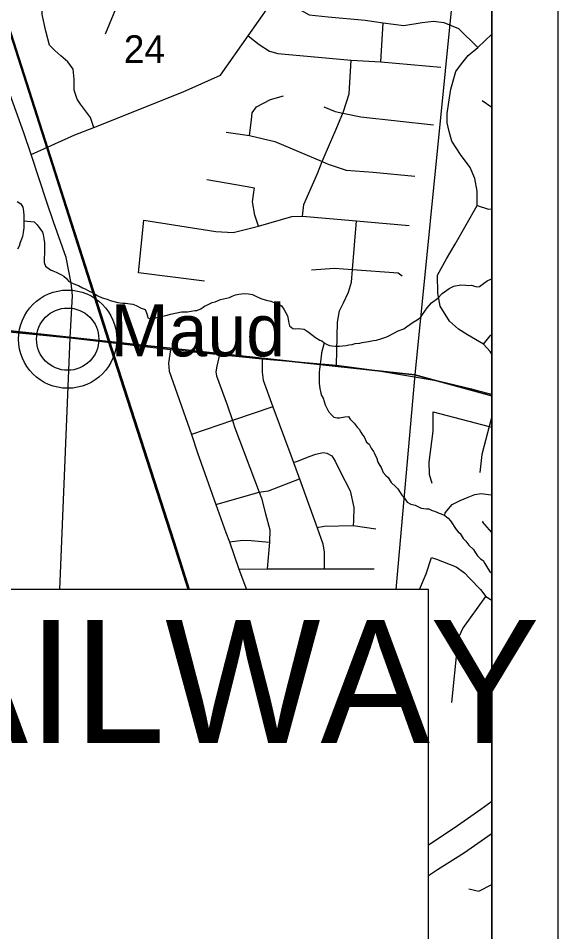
# Model space of a CAD drawing. Extents: x 0 to 34, y 0 to 22.
# Drawn here: x 8.182 to 9, y 18.207 to 19.591 of the extents above; entities that cross this region are included whole.
import ezdxf

# ---------------------------------------------------------------- set-up
doc = ezdxf.new("R2010")
doc.units = 0
for name, color, linetype in [('Default', 7, 'Continuous'), ('GM_X_County_Road', 7, 'Continuous'), ('GM_X_Interstate_Route', 7, 'Continuous'), ('GM_X_Minor_River', 7, 'Continuous'), ('GM_X_Rail_Line', 7, 'Continuous'), ('GM_X_Section', 7, 'Continuous'), ('GM_X_Section_Text', 7, 'Continuous'), ('GM_X_Township_Road', 7, 'Continuous'), ('GM_X_Unincorporated', 7, 'Continuous'), ('GM_X_Unincorporated_Location', 7, 'Continuous'), ('GM_X_Unincorporated_Text', 7, 'Continuous'), ('SH_Cut_Line', 7, 'Continuous'), ('SH_Data', 7, 'Continuous'), ('SH_Text', 7, 'Continuous')]:
    doc.layers.add(name, color=color, linetype=linetype)

msp = doc.modelspace()

# ---------------------------------------------------------------- linework, layer by layer
at = {"layer": 'Default'}
msp.add_lwpolyline([(8.9, 19.0188), (8.9, 19.9702), (8.8752, 19.9725), (8.7834, 19.051)], close=True, dxfattribs=at)
msp.add_lwpolyline([(8.7045, 18.1592), (8.6934, 18.0333), (8.9, 17.9772), (8.9, 19.0188), (8.7834, 19.051), (8.7546, 18.7255)], dxfattribs=at)
at = {"layer": 'GM_X_County_Road'}
for p, q in [((8.2452, 18.7255), (8.261, 19.1068)), ((8.8766, 19.0276), (8.9, 19.0217))]:
    msp.add_line(p, q, dxfattribs=at)
for points in [[(8.5308, 19.5646), (8.5777, 19.6316), (8.6345, 19.7128)], [(8.2019, 19.3849), (8.2683, 19.4144), (8.2969, 19.4257), (8.4325, 19.4794), (8.4891, 19.5049), (8.5308, 19.5646)], [(8.261, 19.1068), (8.2646, 19.1709), (8.2625, 19.1897), (8.2552, 19.2287), (8.2359, 19.2826), (8.2259, 19.3127), (8.2019, 19.3849)], [(7.9926, 19.134), (8.0146, 19.1319), (8.0648, 19.1263), (8.261, 19.1068)], [(8.261, 19.1068), (8.413, 19.089), (8.4873, 19.0817), (8.5519, 19.075), (8.6646, 19.0656), (8.7258, 19.0576), (8.8186, 19.0419), (8.8692, 19.0295), (8.8766, 19.0276)]]:
    msp.add_lwpolyline(points, dxfattribs=at)
at = {"layer": 'GM_X_Interstate_Route'}
for points in [[(8.8041, 18.3388), (8.8432, 18.3646), (8.8836, 18.3928), (8.9, 18.405)], [(8.8041, 18.2924), (8.818, 18.3014), (8.8585, 18.3272), (8.8989, 18.3555), (8.9, 18.3563)]]:
    msp.add_lwpolyline(points, dxfattribs=at)
at = {"layer": 'GM_X_Minor_River'}
for points in [[(8.1807, 19.3137), (8.1862, 19.3097), (8.1895, 19.3047), (8.1905, 19.2986), (8.1907, 19.2921), (8.1906, 19.2887), (8.1908, 19.2841), (8.1906, 19.2784), (8.1909, 19.2735), (8.1904, 19.2701), (8.1899, 19.2663), (8.1886, 19.2606), (8.1873, 19.2565), (8.1853, 19.2512), (8.1836, 19.2459), (8.1812, 19.2411)], [(8.1908, 19.2841), (8.2067, 19.2825), (8.2112, 19.2782), (8.2152, 19.2724), (8.2192, 19.2669), (8.2202, 19.2635), (8.2212, 19.2573), (8.2221, 19.2509), (8.222, 19.2467), (8.2222, 19.2413), (8.2216, 19.2208), (8.2238, 19.2155), (8.2312, 19.2099), (8.2349, 19.2083), (8.2398, 19.2062), (8.244, 19.2046), (8.2477, 19.2026), (8.2514, 19.2002), (8.2555, 19.1966), (8.2584, 19.1927), (8.2622, 19.1907), (8.2689, 19.1875), (8.2734, 19.1862), (8.2798, 19.1829), (8.2839, 19.1813), (8.2907, 19.1769), (8.2952, 19.1756), (8.3019, 19.1709), (8.3094, 19.1676), (8.3173, 19.1655), (8.3214, 19.1634), (8.3331, 19.1604), (8.3407, 19.1594), (8.3449, 19.1593), (8.3521, 19.1583), (8.3562, 19.1578), (8.3611, 19.1561), (8.3686, 19.1521), (8.3746, 19.15), (8.3768, 19.145), (8.3778, 19.1416), (8.3788, 19.1374), (8.3837, 19.1353), (8.3894, 19.1366), (8.394, 19.138), (8.4078, 19.1414), (8.4132, 19.1428), (8.4296, 19.1461), (8.4391, 19.1465), (8.4498, 19.1481), (8.4532, 19.1484), (8.459, 19.1509), (8.4645, 19.1549), (8.4683, 19.1563), (8.476, 19.1602), (8.4806, 19.1616), (8.4887, 19.1648), (8.4933, 19.1662), (8.5025, 19.1682), (8.5067, 19.1699), (8.5117, 19.1721), (8.5167, 19.173), (8.5247, 19.1743), (8.5312, 19.1737), (8.5372, 19.1724), (8.5413, 19.1704), (8.55, 19.1667), (8.5579, 19.1642), (8.5654, 19.1624), (8.5729, 19.1592), (8.5774, 19.1579), (8.5815, 19.1555), (8.5848, 19.1501), (8.5881, 19.145), (8.5906, 19.14), (8.5919, 19.1324), (8.5922, 19.1289), (8.5932, 19.1251), (8.5984, 19.1211), (8.6018, 19.1203), (8.6068, 19.1209), (8.6113, 19.1207), (8.6155, 19.1199), (8.6218, 19.1159), (8.633, 19.1072), (8.6393, 19.1035), (8.6427, 19.1023), (8.646, 19.0995), (8.6494, 19.0972), (8.6543, 19.0951), (8.6577, 19.0946), (8.6634, 19.0941), (8.6691, 19.0943), (8.674, 19.0949), (8.6794, 19.0955), (8.6836, 19.0961), (8.6885, 19.0967), (8.6931, 19.0981), (8.7, 19.099), (8.7038, 19.0997), (8.713, 19.1013)], [(8.713, 19.1013), (8.721, 19.1029), (8.7252, 19.1036), (8.7321, 19.1056), (8.7394, 19.1077), (8.7429, 19.1095), (8.7514, 19.1138), (8.7583, 19.1174), (8.7668, 19.1206), (8.771, 19.1238), (8.7807, 19.1308), (8.7869, 19.1344), (8.7924, 19.1384), (8.7951, 19.1421), (8.8023, 19.1525), (8.8086, 19.1599), (8.8183, 19.1672), (8.825, 19.1743), (8.8355, 19.1819), (8.8424, 19.1851), (8.8531, 19.1871), (8.8607, 19.1869), (8.8649, 19.1864), (8.8691, 19.1866), (8.8736, 19.1853), (8.8773, 19.1841), (8.8812, 19.1847), (8.8877, 19.1891), (8.8932, 19.1935), (8.8986, 19.1956), (8.9, 19.1961)], [(8.646, 19.0995), (8.6418, 19.0841), (8.6412, 19.0784), (8.6388, 19.0595), (8.6382, 19.0542), (8.6384, 19.0454), (8.6385, 19.0382), (8.6391, 19.0336), (8.6394, 19.0302), (8.6407, 19.0233), (8.6422, 19.0194), (8.6443, 19.0156), (8.6474, 19.0052), (8.6525, 18.9952), (8.6569, 18.9901), (8.6606, 18.9866), (8.6655, 18.9857), (8.6693, 18.9855), (8.6773, 18.9872), (8.683, 18.9878), (8.6856, 18.9839), (8.6915, 18.9777), (8.6959, 18.9718), (8.6988, 18.9683), (8.7017, 18.964), (8.7043, 18.9602), (8.7068, 18.9567), (8.71, 18.949), (8.7141, 18.9458), (8.717, 18.9396), (8.7206, 18.9349), (8.7224, 18.9315), (8.7256, 18.9242), (8.7274, 18.9184), (8.7306, 18.9137), (8.7324, 18.9103), (8.7356, 18.9029), (8.7393, 18.8983), (8.743, 18.8951), (8.7474, 18.8878), (8.7544, 18.8811), (8.7577, 18.8783), (8.761, 18.8725), (8.7639, 18.8686), (8.7679, 18.8639), (8.772, 18.8581), (8.7772, 18.8549), (8.784, 18.8532), (8.7881, 18.8512), (8.793, 18.8491), (8.8009, 18.8477), (8.8047, 18.8476), (8.8096, 18.8452), (8.813, 18.8443), (8.8201, 18.8414), (8.8235, 18.8402), (8.8291, 18.8377), (8.8339, 18.8338), (8.8373, 18.8299), (8.846, 18.8167), (8.8489, 18.8128), (8.8523, 18.8104), (8.8566, 18.8027), (8.8607, 18.7988), (8.8654, 18.7929), (8.8721, 18.7863), (8.8754, 18.7812), (8.8786, 18.7765), (8.8827, 18.7722), (8.8868, 18.7695), (8.8897, 18.7648), (8.8926, 18.7598), (8.8966, 18.7532), (8.9, 18.7502)], [(8.8291, 18.8377), (8.8294, 18.8418), (8.84, 18.8545), (8.8519, 18.8603), (8.8642, 18.8653), (8.8745, 18.8696), (8.884, 18.8709), (8.895, 18.8694), (8.9, 18.8692)]]:
    msp.add_lwpolyline(points, dxfattribs=at)
at = {"layer": 'GM_X_Rail_Line'}
for points in [[(8.4398, 18.7255), (8.417, 18.7971), (8.3229, 19.0903), (8.2261, 19.3934), (8.0982, 19.7915), (8.0194, 20.0387), (7.8397, 20.5967), (7.7636, 20.8402), (7.7444, 20.9)], [(8.4419, 18.7255), (8.4189, 18.7977), (8.3247, 19.0909), (8.2279, 19.394), (8.1001, 19.7921), (8.0212, 20.0393), (7.8415, 20.5972), (7.7654, 20.8408), (7.7464, 20.9)]]:
    msp.add_lwpolyline(points, dxfattribs=at)
at = {"layer": 'GM_X_Section'}
msp.add_lwpolyline([(7.8637, 20.0659), (8.8506, 19.9738), (8.8752, 19.9725), (8.7834, 19.051), (7.7938, 19.1583)], close=True, dxfattribs=at)
msp.add_lwpolyline([(7.7552, 18.7255), (7.7938, 19.1583), (8.7834, 19.051), (8.7546, 18.7255)], dxfattribs=at)
at = {"layer": 'GM_X_Township_Road'}
for p, q in [((8.3323, 19.6107), (8.3141, 19.5672)), ((8.7319, 19.5251), (8.7355, 19.5843)), ((8.9, 19.4557), (8.8856, 19.4661))]:
    msp.add_line(p, q, dxfattribs=at)
for points in [[(8.9, 14.8595), (8.9, 19.9667), (8.8165, 19.9737), (8.7085, 19.9845), (8.6673, 19.9886), (7.9584, 20.0596), (7.8238, 20.073), (7.7765, 20.0797), (7.7604, 20.0801), (7.4871, 20.1047), (7.4148, 20.1115), (7.0596, 20.1449), (6.9284, 20.155), (6.8864, 20.1589), (6.8656, 20.1588), (6.8473, 20.1572), (6.8137, 20.1565), (6.8112, 20.1567), (6.7658, 20.1595), (6.7526, 20.1604), (6.71, 20.1637), (6.6784, 20.1674), (6.4945, 20.1803)], [(8.2019, 19.3849), (8.1906, 19.4173), (8.1328, 19.5778), (8.1185, 19.6074), (8.1051, 19.6338), (8.0979, 19.6497), (8.0885, 19.673), (8.0618, 19.7259), (8.0472, 19.7513), (8.0345, 19.7741), (8.0218, 19.7987), (8.0153, 19.8143), (8.0057, 19.8401), (7.996, 19.8652), (7.9885, 19.8873), (7.9832, 19.9061), (7.9805, 19.9239), (7.9729, 19.994), (7.9667, 20.0283), (7.9624, 20.049)], [(8.2969, 19.4257), (8.2919, 19.4405), (8.2769, 19.4607), (8.2716, 19.4687), (8.267, 19.4822), (8.2672, 19.4989), (8.2658, 19.5139), (8.2574, 19.5249), (8.2469, 19.5339), (8.2378, 19.542), (8.2297, 19.5504), (8.2241, 19.5714), (8.2185, 19.597), (8.2188, 19.6159), (8.2259, 19.6293), (8.2353, 19.6419), (8.2439, 19.6505)], [(8.5777, 19.6316), (8.5917, 19.6205), (8.6117, 19.603), (8.6233, 19.5965), (8.6518, 19.5933), (8.7083, 19.5881), (8.7355, 19.5843), (8.7667, 19.5799), (8.7947, 19.5848), (8.8119, 19.5866), (8.8273, 19.5848), (8.8494, 19.5754), (8.8788, 19.547)], [(8.5308, 19.5646), (8.5475, 19.5513), (8.5632, 19.5414), (8.5757, 19.5375), (8.687, 19.5276), (8.7319, 19.5251), (8.8228, 19.5168)], [(8.8876, 19.0973), (8.8631, 19.1114), (8.8497, 19.1199), (8.8357, 19.1323), (8.822, 19.1547), (8.8182, 19.1747), (8.8178, 19.2017), (8.8312, 19.2266), (8.8445, 19.249), (8.8778, 19.3076), (8.8778, 19.3293), (8.8743, 19.3482), (8.8673, 19.365), (8.8525, 19.3847), (8.8396, 19.4047), (8.8354, 19.4197), (8.8322, 19.4324), (8.8326, 19.4467), (8.835, 19.4639), (8.8378, 19.4835), (8.8455, 19.5105), (8.8539, 19.5221), (8.8641, 19.5347), (8.8788, 19.547), (8.9, 19.5668)], [(8.6555, 19.4031), (8.6625, 19.4195), (8.6742, 19.4473), (8.6752, 19.4497), (8.6838, 19.4767), (8.687, 19.5276)], [(8.5328, 19.4133), (8.5358, 19.4372), (8.5371, 19.4477), (8.5433, 19.4571), (8.5646, 19.4678), (8.5843, 19.4734)], [(8.6454, 19.4569), (8.6625, 19.4497), (8.6742, 19.4473), (8.7014, 19.4417), (8.8118, 19.4298)], [(8.4973, 19.4185), (8.5328, 19.4133), (8.5712, 19.4042), (8.607, 19.3893), (8.6431, 19.374), (8.6522, 19.3701), (8.6791, 19.361), (8.7201, 19.3579), (8.7834, 19.3516)], [(8.6134, 19.2913), (8.6152, 19.3089), (8.6358, 19.3561), (8.6431, 19.374), (8.6555, 19.4031)], [(8.5465, 19.2763), (8.5408, 19.2927), (8.5376, 19.3131), (8.5393, 19.3276), (8.5403, 19.3339), (8.5121, 19.3388), (8.4684, 19.3463)], [(8.8778, 19.3076), (8.8949, 19.3019), (8.9, 19.3022)], [(8.4644, 19.1929), (8.3644, 19.2052), (8.3728, 19.2852), (8.4817, 19.2682), (8.5083, 19.2664), (8.5465, 19.2763), (8.597, 19.2906), (8.6134, 19.2913), (8.6948, 19.284), (8.7119, 19.2826), (8.775, 19.2773)], [(8.6646, 19.0656), (8.6664, 19.1308), (8.6692, 19.148), (8.6751, 19.1599), (8.6828, 19.176), (8.6874, 19.1911), (8.6889, 19.2105), (8.6948, 19.284)], [(8.6268, 19.2097), (8.6614, 19.2124), (8.6889, 19.2105), (8.7583, 19.2055), (8.7641, 19.2009)], [(8.8876, 19.0973), (8.8974, 19.1101), (8.9, 19.1123)], [(8.413, 19.089), (8.41, 19.0686), (8.4109, 19.0562), (8.445, 18.9605), (8.4538, 18.9329), (8.4818, 18.8543), (8.4968, 18.8121), (8.5023, 18.7979), (8.5169, 18.7566), (8.5285, 18.7255)], [(8.9, 19.0822), (8.8974, 19.0864), (8.8876, 19.0973)], [(8.4873, 19.0817), (8.4831, 19.0638), (8.482, 19.0552), (8.4827, 19.0495), (8.4989, 19.0056), (8.5069, 18.9816), (8.5106, 18.9708), (8.5474, 18.8731), (8.5509, 18.8638), (8.557, 18.8405)], [(8.5519, 19.075), (8.5519, 19.0548), (8.5534, 19.0427), (8.5682, 19.0025), (8.5956, 18.9292), (8.5996, 18.9179), (8.6084, 18.8935), (8.6177, 18.8682), (8.6352, 18.8192), (8.6439, 18.7948), (8.6462, 18.782), (8.646, 18.7569)], [(8.5682, 19.0025), (8.5069, 18.9816), (8.445, 18.9605)], [(8.8098, 18.8862), (8.8056, 18.8999), (8.8052, 18.9185), (8.811, 18.9656), (8.811, 18.9946)], [(8.811, 18.9946), (8.8961, 18.9727), (8.9, 18.9717)], [(8.9, 18.9878), (8.8961, 18.9727), (8.8848, 18.93), (8.882, 18.903)], [(8.5996, 18.9179), (8.6072, 18.9208), (8.6233, 18.9271), (8.6336, 18.9305), (8.6446, 18.9333), (8.6502, 18.9322), (8.6574, 18.9282), (8.6625, 18.9199), (8.6699, 18.9052), (8.6853, 18.8752), (8.6909, 18.85), (8.6907, 18.8304), (8.69, 18.822)], [(8.5505, 18.8735), (8.5617, 18.8749), (8.6084, 18.8935)], [(8.4818, 18.8543), (8.5474, 18.8731), (8.5505, 18.8735)], [(8.557, 18.8405), (8.5634, 18.8161), (8.5629, 18.7972), (8.5596, 18.7567)], [(8.7244, 18.8172), (8.69, 18.822), (8.6462, 18.8212), (8.6352, 18.8192)], [(8.9, 18.8121), (8.886, 18.8279), (8.8872, 18.8289)], [(8.5023, 18.7979), (8.5229, 18.8004), (8.5351, 18.7997), (8.5629, 18.7972)], [(8.7903, 18.7255), (8.8008, 18.7495), (8.8087, 18.774)], [(8.8087, 18.774), (8.8163, 18.7714), (8.8462, 18.76), (8.8588, 18.7509), (8.8669, 18.7421), (8.8827, 18.7257), (8.8911, 18.7151), (8.9, 18.7095)], [(8.5169, 18.7566), (8.5596, 18.7567), (8.646, 18.7569), (8.7217, 18.7571)], [(8.8397, 18.5544), (8.848, 18.6391), (8.8511, 18.6552), (8.856, 18.6664), (8.8911, 18.7151)], [(8.8653, 18.2721), (8.8806, 18.2684), (8.9, 18.2786)]]:
    msp.add_lwpolyline(points, dxfattribs=at)
at = {"layer": 'GM_X_Unincorporated'}
for radius in [0.0744, 0.0472]:
    msp.add_circle((8.2572, 19.1049), radius, dxfattribs=at)
at = {"layer": 'GM_X_Unincorporated_Location'}
msp.add_line((8.2572, 19.1049), (8.2572, 19.1049), dxfattribs=at)
at = {"layer": 'SH_Cut_Line'}
msp.add_lwpolyline([(8.9, 14.8595), (8.9, 20.9), (2.1, 20.9), (2.1, 19.3633)], dxfattribs=at)
at = {"layer": 'SH_Data'}
for p, q in [((9, 21), (9, 14)), ((8.9, 20.9), (8.9, 14.1))]:
    msp.add_line(p, q, dxfattribs=at)
at = {"layer": 'SH_Text'}
msp.add_lwpolyline([(8.8041, 18.7255), (5.1102, 18.7255), (5.1102, 18.1592), (8.8041, 18.1592)], close=True, dxfattribs=at)

# ---------------------------------------------------------------- texts
at = {"layer": 'GM_X_Section_Text'}
msp.add_text('24', height=0.04186, rotation=0, dxfattribs=at).set_placement((8.3424, 19.5234))
at = {"layer": 'GM_X_Unincorporated_Text'}
msp.add_text('Maud', height=0.07898, rotation=0, dxfattribs=at).set_placement((8.3224, 19.0789))
at = {"layer": 'SH_Text'}
msp.add_text('NORFOLK SOUTHERN RAILWAY', height=0.18634, dxfattribs=at).set_placement((5.1099, 18.4929))

doc.saveas('drawing.dxf')
